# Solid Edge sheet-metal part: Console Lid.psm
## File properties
Author: m_hel
Template: iso metric sheet metal.psm
Last saved by: m_hel
Revision: 7
Application: Solid Edge
Accuracy: 0,990
Material Thickness: 0,25 cm
Bend Radius: 0,10 cm
Relief Width: 0,10 cm
Relief Length: 0,00 cm
Neutral Factor: 0,330
Minimum Arc Length: 0,01 cm
Deviational Tolerance: 0,01 cm
Username: m_hel
Material: Glass Fiber
Face Style: White (dull)
Fill Style: ANSI36(Marble)
Virtual Style: ANSI36(Marble)
Grouping: Uncategorized
LibraryName: Custom Materials
Coef. of Thermal Exp: 0.0
Thermal Conductivity: 0.0
Specific Heat: 0.0
Modulus of Elasticity: 0.0
Poisson's Ratio: 0.0
Yield Stress: 0.0
Ultimate Stress: 0.0
Elongation: 0.0
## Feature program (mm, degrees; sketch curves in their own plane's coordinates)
base tab "unnamed BaseTab 1"
bead "Bead_2"
sketch for "unnamed Cutout 1" plane through (-101.294, 0, 2.5) normal (0, 0, 1) x-axis (0, 1, 0)
  circle centre (0, 8.706) radius 35
extrude "unnamed Cutout 1" cut
louver "Louver_2"  LouverDepth = 7.5 mm; LouverHeight = 5 mm
louver "Louver_3"  LouverDepth = 7.5 mm; LouverHeight = 5 mm
louver "Louver_4"  LouverDepth = 7.5 mm; LouverHeight = 5 mm
mirror "unnamed Mirror 1" of "Louver_4" about plane through (0, 0, 0) normal (0, -1, 0)
louver "unnamed Louver 1"
flange "Flange_13"
flange "Flange_14"
flange "Flange_15"
flange "Flange_16"
flange "Flange_17"
flange "Flange_18"
close corner "CloseCorner_4"
base feature "unnamed BaseFeature 1"
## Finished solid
Body 1: solid body, 107 faces, 266 edges, 160 vertices.
  Faces by surface: plane 66, cylinder 25, sphere 16
  Edges by curve: line 168, circle 82, ellipse 16
Bounding box of the edges (mm; curved faces can reach further): 340.000 x 340.000 x 30.000, from (-170, -170, -17.5) to (170, 170, 12.5).
Cylindrical faces by radius (mm): R1 x6, R2.5 x4, R3.5 x6, R5.625 x4, R8.125 x4, R35 x1
Spherical faces by radius (mm): R5.625 x8, R8.125 x8
Planar faces by outward normal: +x 12, +y 9, +z 3, -x 12, -y 9, -z 9, oblique 12
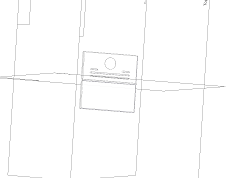
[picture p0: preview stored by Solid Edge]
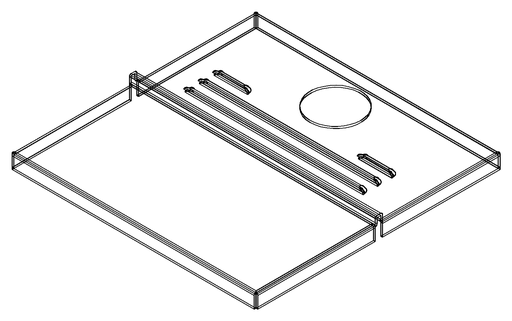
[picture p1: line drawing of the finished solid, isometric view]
